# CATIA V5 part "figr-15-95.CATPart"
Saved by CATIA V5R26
Part number: Part1
Bounding box of the stored display mesh (mm): x -40 to 40, y -60 to 60, z -4 to 2
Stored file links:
  D:\_Deepak\CATIA\CATIA V5 2015 Parts Files\Part files\Partfiles\c15_catia_v5_6r2015_prt\figr-15-95.CATPart
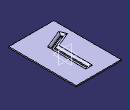
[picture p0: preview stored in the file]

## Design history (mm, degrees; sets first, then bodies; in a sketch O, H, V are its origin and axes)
SheetMetalParameters1: Thickness 2, BendRadius 4, KFactor 0.400515 {= log(min(100,max(20*SheetMetalParameters1.BendRadius,SheetMetalParameters1.Thickness)/SheetMetalParameters1.Thickness))/log(100)/2}, ReliefRadialLength 1, ReliefAxialLength 2, MinimumBendRadius 0
Body1 (main body)
  Sketch1 on xy-plane, origin (0, 0, 0), H (-1, 0, 0), V (0, -1, 0)
    line L1 (40, 60) -> (40, -60)
    line L2 (40, -60) -> (-40, -60)
    line L3 (-40, -60) -> (-40, 60)
    line L4 (-40, 60) -> (40, 60)
    length L4 = 80
    length L1 = 120
    vertical: L1 V, L3 V
    horizontal: L2 H, L4 H
    equidistance: L1 L3 O, L2 L4 O
  Wall1: Thickness 2, Profile Sketch1, OffsetValue 0
  Sketch2 on face of Wall1, origin (0, 0, 2), H (1, 0, 0), V (0, 1, 0)
    line L1 (0, 40.0798) -> (0, -21.0085)
    line L2 (0, -21.0085) -> (-27, -32)
    vertical: L1 V
  d_Stamp1: NewRoot_AttribNormalisation "No Standard", Stamp_FilletRadius 2, Stamp_IntersectFilletRadius 2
